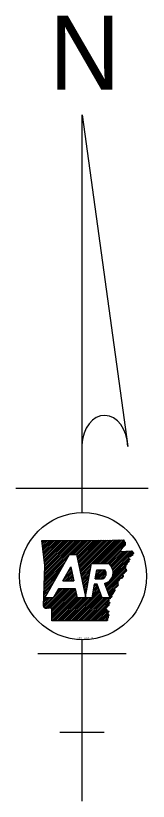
# Model space of a CAD drawing. Extents: x -35254 to 17396, y -8913 to 11592.
# Drawn here: x -3968 to -3442, y -6402 to -3290 of the extents above; entities that cross this region are included whole.
import ezdxf

# ---------------------------------------------------------------- set-up
doc = ezdxf.new("R2010")
doc.units = 0
doc.layers.add('R_Annotation', color=7, linetype='Continuous')

msp = doc.modelspace()

# ---------------------------------------------------------------- linework, layer by layer
at = {"layer": 'R_Annotation'}
for p, q in [((-3704.6, -3682.9), (-3522.8, -4997)), ((-3704.6, -5258.8), (-3704.6, -3682.9)), ((-3967.9, -5161.4), (-3441.6, -5161.4)), ((-3864.3, -5371.7), (-3862.1, -5369.5)), ((-3863.5, -5377.9), (-3855.2, -5369.5)), ((-3862.8, -5384.1), (-3848.2, -5369.5)), ((-3862, -5390.3), (-3841.3, -5369.5)), ((-3861.2, -5396.5), (-3834.3, -5369.5)), ((-3860.5, -5402.7), (-3827.3, -5369.5)), ((-3859.7, -5408.8), (-3820.4, -5369.5)), ((-3858.9, -5415), (-3813.4, -5369.5)), ((-3858.1, -5421.2), (-3806.5, -5369.5)), ((-3857.4, -5427.4), (-3799.5, -5369.5)), ((-3856.6, -5433.6), (-3792.5, -5369.6)), ((-3855.8, -5439.8), (-3785.6, -5369.6)), ((-3855.1, -5446), (-3778.6, -5369.6)), ((-3854.3, -5452.2), (-3771.6, -5369.6)), ((-3854.1, -5521.6), (-3701.9, -5369.4)), ((-3853.8, -5514.4), (-3708.8, -5369.4)), ((-3853.6, -5507.2), (-3715.8, -5369.5)), ((-3853.5, -5458.4), (-3764.7, -5369.6)), ((-3853.3, -5500), (-3722.8, -5369.5)), ((-3853.1, -5492.8), (-3729.8, -5369.5)), ((-3852.9, -5485.6), (-3736.8, -5369.5)), ((-3852.7, -5464.6), (-3757.7, -5369.5)), ((-3852.6, -5478.4), (-3743.7, -5369.5)), ((-3852.4, -5471.2), (-3750.7, -5369.5)), ((-3750.6, -5425.2), (-3694.9, -5369.4)), ((-3743.6, -5425.2), (-3687.9, -5369.4)), ((-3736.7, -5425.2), (-3680.9, -5369.3)), ((-3729.7, -5425.2), (-3673.8, -5369.2)), ((-3725.4, -5427.8), (-3666.7, -5369.1)), ((-3724.2, -5433.5), (-3659.6, -5369)), ((-3722.9, -5439.3), (-3652.6, -5368.9)), ((-3721.7, -5445), (-3645.5, -5368.8)), ((-3720.5, -5450.7), (-3638.4, -5368.7)), ((-3719.2, -5456.5), (-3631.3, -5368.6)), ((-3718, -5462.2), (-3624.3, -5368.5)), ((-3716.8, -5467.9), (-3617.2, -5368.3)), ((-3715.6, -5473.7), (-3610.1, -5368.2)), ((-3714.3, -5479.4), (-3603, -5368.1)), ((-3713.1, -5485.2), (-3596, -5368)), ((-3711.9, -5490.9), (-3588.9, -5367.9)), ((-3710.6, -5496.6), (-3581.8, -5367.8)), ((-3709.4, -5502.4), (-3574.7, -5367.6)), ((-3661, -5460.9), (-3567.5, -5367.4)), ((-3654.1, -5460.9), (-3560.4, -5367.3)), ((-3647.1, -5460.9), (-3553.3, -5367.1)), ((-3640.1, -5460.9), (-3546.1, -5366.9)), ((-3633.2, -5460.9), (-3539, -5366.8)), ((-3626.2, -5460.9), (-3537.4, -5372.2)), ((-3619.2, -5460.9), (-3534.1, -5375.8)), ((-3612.3, -5460.9), (-3533.2, -5381.9)), ((-3605.3, -5460.9), (-3549.1, -5404.7)), ((-3599, -5461.6), (-3550.5, -5413.1)), ((-3595.2, -5464.8), (-3543.1, -5412.7)), ((-3591.8, -5468.3), (-3535.8, -5412.3)), ((-3588.8, -5472.3), (-3528.4, -5411.9)), ((-3586.2, -5476.7), (-3521.1, -5411.6)), ((-3584, -5481.5), (-3513.7, -5411.2)), ((-3582.4, -5486.9), (-3507.1, -5411.5)), ((-3854.3, -5528.8), (-3760.3, -5434.8)), ((-3852, -5596.8), (-3754.8, -5425.2)), ((-3754.8, -5425.2), (-3725.9, -5425.2)), ((-3582.9, -5508.2), (-3519.7, -5445)), ((-3581.5, -5492.9), (-3503.9, -5415.2)), ((-3581.5, -5499.8), (-3520.5, -5438.8)), ((-3507, -5425.3), (-3500.6, -5419)), ((-3854.8, -5543.2), (-3778.5, -5467)), ((-3854.5, -5536), (-3769.4, -5450.9)), ((-3780.5, -5529.4), (-3748.7, -5473.3)), ((-3753.7, -5482), (-3748.1, -5476.4)), ((-3708.2, -5508.1), (-3668.7, -5468.6)), ((-3707, -5513.8), (-3670.1, -5477)), ((-3667.3, -5460.9), (-3599.9, -5460.9)), ((-3611.7, -5550.9), (-3534.5, -5473.7)), ((-3589, -5521.2), (-3535.8, -5468)), ((-3527.5, -5459.8), (-3518.9, -5451.2)), ((-3855.3, -5557.7), (-3796.7, -5499.1)), ((-3855, -5550.4), (-3787.6, -5483)), ((-3780.2, -5529.4), (-3744.4, -5493.6)), ((-3773.2, -5529.4), (-3743.1, -5499.3)), ((-3771.9, -5514.1), (-3745.6, -5487.9)), ((-3766.2, -5529.4), (-3741.9, -5505.1)), ((-3762.8, -5498.1), (-3746.8, -5482.1)), ((-3705.7, -5519.6), (-3671.6, -5485.5)), ((-3704.5, -5525.3), (-3673.1, -5493.9)), ((-3703.3, -5531.1), (-3674.5, -5502.3)), ((-3652.6, -5521.8), (-3616, -5485.2)), ((-3651.2, -5513.4), (-3623, -5485.2)), ((-3649.8, -5505), (-3629.9, -5485.2)), ((-3648.3, -5496.6), (-3636.9, -5485.2)), ((-3646.8, -5488.1), (-3643.9, -5485.2)), ((-3646.3, -5485.2), (-3614.6, -5485.2)), ((-3645.7, -5521.8), (-3612.1, -5488.3)), ((-3638.7, -5521.8), (-3609.8, -5492.9)), ((-3631.7, -5521.8), (-3608.5, -5498.6)), ((-3624.8, -5521.8), (-3609.1, -5506.1)), ((-3609.8, -5556), (-3533.1, -5479.4)), ((-3607.9, -5561.1), (-3531.8, -5485)), ((-3606, -5566.2), (-3530.5, -5490.7)), ((-3855.7, -5572.1), (-3814.9, -5531.2)), ((-3855.5, -5564.9), (-3805.8, -5515.1)), ((-3780.5, -5529.4), (-3736.7, -5529.4)), ((-3759.3, -5529.4), (-3740.7, -5510.8)), ((-3752.3, -5529.4), (-3739.5, -5516.6)), ((-3745.3, -5529.4), (-3738.2, -5522.3)), ((-3738.4, -5529.4), (-3737, -5528)), ((-3702, -5536.8), (-3676, -5510.8)), ((-3700.8, -5542.5), (-3677.5, -5519.2)), ((-3699.6, -5548.3), (-3679, -5527.6)), ((-3698.4, -5554), (-3680.4, -5536.1)), ((-3652.7, -5521.8), (-3623.7, -5521.8)), ((-3616, -5539.3), (-3594.7, -5596.8)), ((-3615.4, -5540.7), (-3613.3, -5538.6)), ((-3613.6, -5545.8), (-3600.3, -5532.6)), ((-3604.2, -5571.3), (-3562.4, -5529.5)), ((-3602.3, -5576.3), (-3563.2, -5537.2)), ((-3554.3, -5521.5), (-3544.6, -5511.7)), ((-3856.2, -5586.5), (-3833, -5563.3)), ((-3856, -5579.3), (-3824, -5547.3)), ((-3854.9, -5634), (-3781.7, -5560.7)), ((-3850.8, -5636.8), (-3774.8, -5560.7)), ((-3845.8, -5638.7), (-3767.8, -5560.7)), ((-3837.5, -5637.4), (-3760.8, -5560.7)), ((-3830.4, -5637.3), (-3753.9, -5560.7)), ((-3825, -5638.8), (-3746.9, -5560.7)), ((-3824.8, -5645.6), (-3739.9, -5560.7)), ((-3824.7, -5652.5), (-3733, -5560.7)), ((-3824.7, -5659.5), (-3729.3, -5564)), ((-3824.7, -5666.4), (-3728.1, -5569.8)), ((-3798.3, -5560.7), (-3818.6, -5596.8)), ((-3810.7, -5582.8), (-3788.7, -5560.7)), ((-3801.7, -5566.7), (-3795.7, -5560.7)), ((-3730, -5560.7), (-3798.3, -5560.7)), ((-3755, -5687.3), (-3635.2, -5567.5)), ((-3697.1, -5559.8), (-3681.9, -5544.5)), ((-3695.9, -5565.5), (-3683.4, -5552.9)), ((-3694.7, -5571.2), (-3684.8, -5561.4)), ((-3693.5, -5577), (-3686.3, -5569.8)), ((-3664.5, -5589.8), (-3637.1, -5562.4)), ((-3663.1, -5581.4), (-3639, -5557.3)), ((-3661.6, -5573), (-3640.8, -5552.2)), ((-3660.1, -5564.5), (-3642.7, -5547.1)), ((-3658.7, -5556.1), (-3644.7, -5542.2)), ((-3657.2, -5547.7), (-3651.7, -5542.2)), ((-3644.5, -5542.2), (-3656.2, -5542.2)), ((-3624.4, -5596.8), (-3644.5, -5542.2)), ((-3600.4, -5581.4), (-3563.9, -5545)), ((-3598.5, -5586.5), (-3577.2, -5565.2)), ((-3857.5, -5629.6), (-3824.7, -5596.8)), ((-3857.4, -5622.5), (-3831.7, -5596.8)), ((-3857.2, -5615.3), (-3838.6, -5596.8)), ((-3856.9, -5608.1), (-3845.6, -5596.8)), ((-3856.7, -5600.9), (-3851.2, -5595.4)), ((-3856.4, -5593.7), (-3842.1, -5579.4)), ((-3818.6, -5596.8), (-3852, -5596.8)), ((-3824.7, -5673.4), (-3726.8, -5575.5)), ((-3824.7, -5680.3), (-3725.6, -5581.3)), ((-3824.5, -5687.2), (-3724.4, -5587)), ((-3817.6, -5687.2), (-3723.2, -5592.7)), ((-3810.6, -5687.2), (-3720.2, -5596.8)), ((-3803.7, -5687.2), (-3713.2, -5596.8)), ((-3796.7, -5687.2), (-3706.3, -5596.8)), ((-3789.8, -5687.2), (-3699.3, -5596.8)), ((-3782.8, -5687.2), (-3692.3, -5596.8)), ((-3775.9, -5687.2), (-3685.4, -5596.8)), ((-3768.9, -5687.3), (-3678.4, -5596.8)), ((-3762, -5687.3), (-3671.5, -5596.8)), ((-3748.1, -5687.3), (-3633.3, -5572.6)), ((-3741.1, -5687.3), (-3631.4, -5577.6)), ((-3734.1, -5687.3), (-3629.6, -5582.7)), ((-3727.2, -5687.3), (-3627.7, -5587.8)), ((-3665.7, -5596.8), (-3722.3, -5596.8)), ((-3720.2, -5687.3), (-3625.8, -5592.9)), ((-3713.3, -5687.3), (-3622.7, -5596.8)), ((-3706.3, -5687.4), (-3615.7, -5596.8)), ((-3699.4, -5687.4), (-3608.8, -5596.8)), ((-3692.4, -5687.4), (-3601.8, -5596.8)), ((-3692.2, -5582.7), (-3687.8, -5578.2)), ((-3691, -5588.4), (-3689.2, -5586.7)), ((-3685.5, -5687.4), (-3599.5, -5601.4)), ((-3594.7, -5596.8), (-3624.4, -5596.8)), ((-3596.6, -5591.6), (-3580.1, -5575.1)), ((-3678.5, -5687.4), (-3599.2, -5608)), ((-3671.6, -5687.4), (-3598.8, -5614.7)), ((-3664.6, -5687.4), (-3598.5, -5621.4)), ((-3657.6, -5687.4), (-3610, -5639.8)), ((-3650.7, -5687.4), (-3607.8, -5644.6)), ((-3643.7, -5687.5), (-3605.7, -5649.4)), ((-3636.8, -5687.5), (-3603.5, -5654.2)), ((-3629.8, -5687.5), (-3601.4, -5659)), ((-3622.9, -5687.5), (-3599.6, -5664.2)), ((-3615.9, -5687.5), (-3602.7, -5674.3)), ((-3609, -5687.5), (-3605.9, -5684.4)), ((-3704.6, -6402.5), (-3704.6, -5762.9)), ((-3880.1, -5817.3), (-3529.2, -5817.3)), ((-3792.4, -6128.8), (-3616.9, -6128.8))]:
    msp.add_line(p, q, dxfattribs=at)
for points in [[(-3864.6, -5369.6), (-3768.5, -5369.6), (-3684.1, -5369.4), (-3584.7, -5367.9), (-3538.5, -5366.8)], [(-3864.6, -5369.5), (-3768.5, -5369.6), (-3684.2, -5369.4), (-3584.7, -5367.8), (-3538.5, -5366.8)], [(-3857.6, -5629.5), (-3852.3, -5468.3), (-3864.6, -5369.5)], [(-3854, -5518.9), (-3852.3, -5468.3), (-3864.6, -5369.6)], [(-3508.4, -5410.9), (-3500, -5419.6), (-3520.8, -5436.7), (-3518.5, -5453.9), (-3536.3, -5465.6), (-3530.2, -5492), (-3543.9, -5504.5), (-3545.2, -5518.1), (-3561.8, -5524.1), (-3564.4, -5549.8), (-3576.4, -5562.6), (-3582.2, -5581.9), (-3599.6, -5597.9), (-3598.3, -5626.1), (-3610.2, -5639.3), (-3599.4, -5663.5), (-3606.8, -5687.5)], [(-3552.8, -5413.2), (-3507.7, -5410.9)], [(-3552.8, -5413.2), (-3507.7, -5410.9)], [(-3725.9, -5425.2), (-3690.2, -5592.2), (-3667.3, -5460.9)], [(-3748.7, -5473.3), (-3736.7, -5529.4)], [(-3652.7, -5521.8), (-3646.3, -5485.2)], [(-3857.6, -5629.5), (-3854, -5518.9)], [(-3722.3, -5596.8), (-3730, -5560.7)], [(-3656.2, -5542.2), (-3665.7, -5596.8)], [(-3606.8, -5687.5), (-3824.7, -5687.2), (-3824.8, -5639.1)], [(-3606.9, -5687.5), (-3824.7, -5687.2), (-3824.7, -5639.1)]]:
    msp.add_lwpolyline(points, dxfattribs=at)
for centre, major_axis, ratio, start_param, end_param in [((-3613.8, -4999.9), (-3.9, 126.3), 0.719778, 4.712385, 7.768526), ((-3624.9, -5496.6), (-43.6, 0), 0.999987, 1.777838, 4.099264), ((-3630.7, -5500.6), (-22.3, 0), 0.999987, 1.887169, 3.90762)]:
    msp.add_ellipse(centre, major_axis=major_axis, ratio=ratio, start_param=start_param, end_param=end_param, dxfattribs=at)
msp.add_ellipse((-3700.6, -5510.8), major_axis=(252.1, 0), ratio=0.999976, dxfattribs=at)
for points in [[(-3538.5, -5366.8), (-3538.3, -5369.4), (-3537.5, -5370.7), (-3537.3, -5373.3), (-3536.3, -5374.3), (-3534.5, -5375.4), (-3533.1, -5377.1), (-3532.7, -5379.1), (-3533.2, -5381.2), (-3533.3, -5383.6), (-3533.5, -5385.6), (-3533.9, -5387.4), (-3535.3, -5388.9), (-3536.6, -5389.9), (-3537.9, -5391.2), (-3538.8, -5392.5), (-3540.3, -5393.9), (-3541.9, -5395.4), (-3543.2, -5396.7), (-3544.4, -5398.4), (-3545, -5400.2), (-3546.3, -5401.5), (-3547.4, -5402.7), (-3548.8, -5404.4), (-3549.5, -5405.9), (-3550.9, -5407.8), (-3551.2, -5409.5), (-3552.1, -5411), (-3552.2, -5411.2)], [(-3538.5, -5366.8), (-3538.3, -5369.4), (-3537.4, -5370.8), (-3537.3, -5373.3), (-3536.3, -5374.3), (-3534.6, -5375.4), (-3533, -5377.1), (-3532.7, -5379.1), (-3533.1, -5381.2), (-3533.3, -5383.5), (-3533.5, -5385.6), (-3533.9, -5387.4), (-3535.3, -5388.9), (-3536.6, -5390), (-3537.9, -5391.2), (-3538.8, -5392.5), (-3540.3, -5393.9), (-3541.9, -5395.4), (-3543.1, -5396.7), (-3544.4, -5398.4), (-3545, -5400.2), (-3546.3, -5401.5), (-3547.4, -5402.7), (-3548.8, -5404.3), (-3549.5, -5405.9), (-3550.9, -5407.8), (-3551.2, -5409.6), (-3552.1, -5411), (-3552.2, -5411.2)], [(-3508.4, -5410.9), (-3507.7, -5410.9), (-3505.7, -5413), (-3504.8, -5414.8), (-3503.5, -5415.8), (-3502, -5416.3), (-3500.9, -5417.7), (-3500.1, -5419.2), (-3500.5, -5420.5), (-3502.2, -5420.6), (-3504, -5420.9), (-3505.8, -5420.8), (-3507.3, -5422.1), (-3505.9, -5423.6), (-3504.2, -5425.2), (-3503.7, -5426.7), (-3504.7, -5428.3), (-3506.6, -5429.1), (-3508.4, -5429.9), (-3510.1, -5431.2), (-3510.9, -5432.6), (-3512.7, -5433.2), (-3514.6, -5433.8), (-3516.3, -5433.9), (-3518.2, -5434.3), (-3520, -5435.2), (-3520.8, -5436.7), (-3520.5, -5438.9), (-3520.6, -5441.2), (-3518.7, -5442), (-3516.9, -5442.1), (-3515.2, -5442.9), (-3515.4, -5444.3), (-3516.7, -5445.9), (-3518.2, -5447.2), (-3519.6, -5447.9), (-3521, -5449.2), (-3520.5, -5450.4), (-3519.3, -5451.2), (-3518.4, -5452.6), (-3518.5, -5453.8), (-3520, -5454.7), (-3521.5, -5454.4), (-3522.7, -5452.9), (-3523.9, -5452.4), (-3525.1, -5451.9), (-3526.4, -5452.6), (-3526.4, -5454.4), (-3526.8, -5456.2), (-3526.4, -5457.6), (-3525.9, -5459.5), (-3526, -5460.9), (-3526.4, -5462.9), (-3527.5, -5465), (-3528.6, -5465.7), (-3529.2, -5463.4), (-3529.3, -5461.6), (-3530.1, -5460.5), (-3531, -5460.4), (-3532.3, -5461.3), (-3533.6, -5462.7), (-3535.3, -5464.2), (-3536.3, -5465.7), (-3535.8, -5467.5), (-3534.5, -5468), (-3533.5, -5467.6), (-3533, -5466.4), (-3532, -5466.3), (-3531, -5468.1)], [(-3531, -5468.1), (-3530.7, -5469.8), (-3531.8, -5471.6), (-3532.2, -5473.5), (-3532, -5475.4), (-3533.9, -5476.4), (-3535.5, -5477.6), (-3534.5, -5479), (-3532.7, -5480.3), (-3531, -5481.3), (-3529.9, -5482.3), (-3529.6, -5484.7), (-3529.3, -5486.3), (-3528.7, -5488.4), (-3528.5, -5489.9), (-3529.5, -5491.7), (-3530.7, -5492.1), (-3532.1, -5491.7), (-3533.6, -5491.5), (-3534.9, -5492.7), (-3535.8, -5494.4), (-3536.6, -5496), (-3537.3, -5497.5), (-3538, -5499), (-3539.3, -5500.8), (-3540.9, -5501.1), (-3542.8, -5501.6), (-3543.9, -5502.9), (-3543.7, -5505.1), (-3542.6, -5506.5), (-3541.8, -5508.4), (-3541.2, -5510), (-3541.5, -5512), (-3542.3, -5513.5), (-3543.4, -5514.4), (-3543.9, -5516.3), (-3544.7, -5517.7), (-3545.4, -5518.2), (-3546.8, -5518.1), (-3548.4, -5517.8), (-3549.7, -5517.9), (-3550.9, -5518.5), (-3552.2, -5518.1), (-3553.5, -5516.7), (-3554.6, -5515.6), (-3555.8, -5515.2), (-3557, -5515.9), (-3557.2, -5517.9), (-3556.6, -5519.9), (-3556.1, -5522.6), (-3556.6, -5524.2), (-3556.8, -5527)], [(-3556.8, -5527), (-3558.9, -5528.6), (-3559.8, -5530.2), (-3565.1, -5529.7), (-3565, -5531.6), (-3566.8, -5532.6), (-3568.5, -5533.8), (-3567.6, -5535.2), (-3565.8, -5536.5), (-3564, -5537.5), (-3562.9, -5538.5), (-3562.6, -5541), (-3562.2, -5542.5), (-3561.7, -5544.7), (-3561.4, -5546.2), (-3562.5, -5547.9), (-3563.8, -5548.3), (-3565, -5547.9), (-3566.6, -5547.8), (-3567.8, -5548.9), (-3568.7, -5550.6), (-3569.6, -5552.3), (-3570.3, -5553.7), (-3571, -5555.3), (-3572.2, -5557.1), (-3573.8, -5557.3), (-3575.7, -5557.8), (-3576.9, -5559.1), (-3576.7, -5561.3), (-3575.6, -5562.8), (-3574.8, -5564.6), (-3574.2, -5566.2), (-3574.5, -5568.2), (-3575.3, -5569.8), (-3576.4, -5570.7), (-3576.9, -5572.5), (-3577.7, -5574), (-3578.4, -5574.4), (-3579.8, -5574.3), (-3581.3, -5574), (-3582.6, -5574.1), (-3583.9, -5574.8), (-3585.1, -5574.4), (-3586.4, -5573), (-3587.5, -5571.9), (-3588.7, -5571.5), (-3590, -5572.1), (-3590.2, -5574.1), (-3589.6, -5576.1), (-3589, -5578.8), (-3589.6, -5580.5), (-3589.7, -5583.3)], [(-3589.7, -5583.3), (-3589.9, -5583.3), (-3591, -5584.7), (-3590.4, -5586.8), (-3588.1, -5587.6), (-3587, -5589.6), (-3586.9, -5591.4), (-3587.7, -5593.8), (-3588.8, -5595), (-3590.8, -5595.5), (-3592.4, -5595.8), (-3592.7, -5598.5), (-3593.4, -5599.9), (-3594.6, -5600.3), (-3596.4, -5599.4), (-3597.5, -5598.9), (-3598.8, -5598.3), (-3600.5, -5597.4), (-3601.8, -5597.6), (-3601.4, -5600.1), (-3601.3, -5600.3), (-3599.8, -5602.2), (-3598.4, -5603.8), (-3597.8, -5605.6)], [(-3589.7, -5583.3), (-3589.9, -5583.3), (-3591, -5584.7), (-3590.4, -5586.8), (-3588.1, -5587.6), (-3587, -5589.6), (-3586.9, -5591.4), (-3587.7, -5593.8), (-3588.8, -5595), (-3590.8, -5595.5), (-3592.4, -5595.8), (-3592.7, -5598.5), (-3593.4, -5599.9), (-3594.6, -5600.3), (-3596.4, -5599.4), (-3597.5, -5598.9), (-3598.8, -5598.3), (-3600.5, -5597.4), (-3601.8, -5597.6), (-3601.4, -5600.1), (-3601.3, -5600.3), (-3599.8, -5602.2), (-3598.4, -5603.8), (-3597.8, -5605.6)], [(-3824.7, -5639.1), (-3824.5, -5639.2), (-3825.6, -5638.4), (-3827.2, -5637.7), (-3828.9, -5637.6), (-3831.2, -5637.3), (-3833, -5637.1), (-3834.9, -5635.8), (-3836.9, -5637.1), (-3839.1, -5638.1), (-3840.5, -5637), (-3842.2, -5637.7), (-3843.4, -5637.3), (-3845.4, -5638.8), (-3847.4, -5638.2), (-3848.8, -5638.6), (-3850.6, -5638.6), (-3851, -5636.6), (-3852.7, -5636.3), (-3854.2, -5635.5), (-3855.2, -5633.4), (-3855.9, -5631.7), (-3857.6, -5629.5)], [(-3824.8, -5639.1), (-3824.5, -5639.2), (-3825.7, -5638.4), (-3827.2, -5637.7), (-3828.9, -5637.5), (-3831.1, -5637.2), (-3833, -5637.1), (-3834.9, -5635.8), (-3836.9, -5637.1), (-3839.2, -5638.1), (-3840.5, -5637), (-3842.2, -5637.7), (-3843.4, -5637.4), (-3845.5, -5638.8), (-3847.4, -5638.2), (-3848.8, -5638.7), (-3850.6, -5638.6), (-3851, -5636.6), (-3852.7, -5636.3), (-3854.2, -5635.5), (-3855.2, -5633.4), (-3855.9, -5631.8), (-3857.6, -5629.5)], [(-3597.8, -5605.6), (-3598.3, -5607), (-3599, -5609.4), (-3598.8, -5611.4), (-3597.9, -5613.1), (-3596.5, -5614), (-3594.9, -5615.4), (-3595.1, -5617.5), (-3596, -5618.3), (-3598.1, -5617.8), (-3599.7, -5617), (-3601, -5617.4), (-3602.8, -5618.3), (-3604.2, -5618.6), (-3604.2, -5621.4), (-3602.3, -5623.4), (-3600.7, -5623.4), (-3598.9, -5623.6), (-3598.2, -5625.8), (-3599.3, -5627.6), (-3601.1, -5628.4), (-3603.3, -5627.4), (-3604.9, -5626.2), (-3606.5, -5625.2), (-3608.5, -5624.6), (-3609.7, -5624.9), (-3610.2, -5627.4), (-3609.3, -5629.6), (-3607.7, -5631.2), (-3606.3, -5633.2), (-3606.5, -5634.7), (-3607.6, -5635.1), (-3609.5, -5635.5), (-3610.6, -5636.1), (-3610.9, -5636.6), (-3610.3, -5638.6), (-3609.8, -5640.8), (-3609.8, -5642.5), (-3610.5, -5644), (-3611.5, -5646.3), (-3611.4, -5647.9), (-3610.6, -5648.6), (-3609.8, -5648.4), (-3608.5, -5647.6), (-3607.8, -5646.6), (-3607.1, -5645.4), (-3605.9, -5644.4), (-3604.4, -5645.3), (-3604, -5647.2), (-3604.9, -5648.8), (-3606.1, -5649.5), (-3607.7, -5650.1), (-3608.8, -5651.4), (-3608.5, -5653), (-3607.6, -5653.8), (-3605.4, -5653.3), (-3603.9, -5652.7), (-3603.1, -5651.9), (-3602.1, -5650.9), (-3601.6, -5649.8), (-3600.8, -5648.8), (-3599.4, -5648.5), (-3598.7, -5649.3), (-3599, -5651.4), (-3599.8, -5653.3), (-3601, -5654.9), (-3602.2, -5656), (-3603.8, -5658.4), (-3603.4, -5660.7), (-3602.8, -5662.6), (-3602.1, -5664), (-3600.6, -5663.7), (-3599, -5663.5), (-3598.1, -5664.3), (-3598.2, -5665.9), (-3599.3, -5667.6), (-3600.5, -5669.1), (-3601.1, -5671.2), (-3600.8, -5672.7), (-3600.8, -5674.1), (-3601.3, -5675.6), (-3602.1, -5676.4), (-3604.4, -5676.4), (-3606.7, -5676.1), (-3607.9, -5676.8), (-3607.7, -5678.8), (-3606.3, -5680.3), (-3605.4, -5681.1), (-3604, -5682.8), (-3603.4, -5684.1), (-3603.6, -5685.3), (-3604.4, -5686.4), (-3606.9, -5687.5)], [(-3597.8, -5605.6), (-3598.3, -5607), (-3599, -5609.4), (-3598.8, -5611.4), (-3597.9, -5613.1), (-3596.5, -5614), (-3594.9, -5615.4), (-3595.1, -5617.5), (-3596, -5618.3), (-3598.1, -5617.8), (-3599.7, -5617), (-3601, -5617.4), (-3602.8, -5618.3), (-3604.2, -5618.6), (-3604.2, -5621.4), (-3602.3, -5623.4), (-3600.7, -5623.4), (-3598.9, -5623.6), (-3598.2, -5625.8), (-3599.3, -5627.6), (-3601.1, -5628.4), (-3603.3, -5627.4), (-3604.9, -5626.2), (-3606.5, -5625.2), (-3608.5, -5624.6), (-3609.7, -5624.9), (-3610.2, -5627.4), (-3609.3, -5629.6), (-3607.7, -5631.2), (-3606.3, -5633.2), (-3606.5, -5634.7), (-3607.6, -5635.1), (-3609.5, -5635.5), (-3610.6, -5636.1), (-3610.9, -5636.6), (-3610.3, -5638.6), (-3609.8, -5640.8), (-3609.8, -5642.5), (-3610.5, -5644), (-3611.5, -5646.3), (-3611.4, -5647.9), (-3610.6, -5648.6), (-3609.8, -5648.4), (-3608.5, -5647.6), (-3607.8, -5646.6), (-3607.1, -5645.4), (-3605.9, -5644.4), (-3604.4, -5645.3), (-3604, -5647.2), (-3604.9, -5648.8), (-3606.1, -5649.5), (-3607.7, -5650.1), (-3608.8, -5651.4), (-3608.5, -5653), (-3607.6, -5653.8), (-3605.4, -5653.3), (-3603.9, -5652.7), (-3603.1, -5651.9), (-3602.1, -5650.9), (-3601.6, -5649.8), (-3600.8, -5648.8), (-3599.4, -5648.5), (-3598.7, -5649.3), (-3599, -5651.4), (-3599.8, -5653.3), (-3601, -5654.9), (-3602.2, -5656), (-3603.8, -5658.4), (-3603.4, -5660.7), (-3602.8, -5662.6), (-3602.1, -5664), (-3600.6, -5663.7), (-3599, -5663.5), (-3598.1, -5664.3), (-3598.2, -5665.9), (-3599.3, -5667.6), (-3600.5, -5669.1), (-3601.1, -5671.2), (-3600.8, -5672.7), (-3600.8, -5674.1), (-3601.3, -5675.6), (-3602.1, -5676.4), (-3604.4, -5676.4), (-3606.7, -5676.1), (-3607.9, -5676.8), (-3607.7, -5678.8), (-3606.3, -5680.3), (-3605.4, -5681.1), (-3604, -5682.8), (-3603.4, -5684.1), (-3603.6, -5685.3), (-3604.4, -5686.4), (-3606.9, -5687.5)]]:
    msp.add_spline(points, degree=3, dxfattribs=at)

# ---------------------------------------------------------------- texts
for s, height, p in [('N', 293.3, (-3835.4, -3583.7)), ('STS 10-03-17', 7.288, (-3724.7, -5760.9))]:
    msp.add_text(s, height=height, dxfattribs=at).set_placement(p)

doc.saveas('drawing.dxf')
